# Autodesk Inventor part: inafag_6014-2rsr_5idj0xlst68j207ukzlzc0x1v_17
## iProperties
Shininess: 64.0
Angle Display Precision: 2
Document Length Units: 11269
Document Angle Units: 11279
Document Time Units: 11290
Document Mass Units: 11283
Document Length Units Precision: 3
Document Angle Units Precision: 2
Compacted: True
Created: 2008-08
Part Number: inafag_6014-2rsr_5idj0xlst68j207ukzlzc0x1v_17
Document SubType Name: Modeling
Designer: tpomodeler
Density: 0.0
Volumn: 0.0
Area: 0.0
PropertySet Name: Model Information
Control State: 0
Master: False
Checked Out: False
Author: tpomodeler
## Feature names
1. inafag_6014-2rsr_5idj0xlst68j207ukzlzc0x1v
